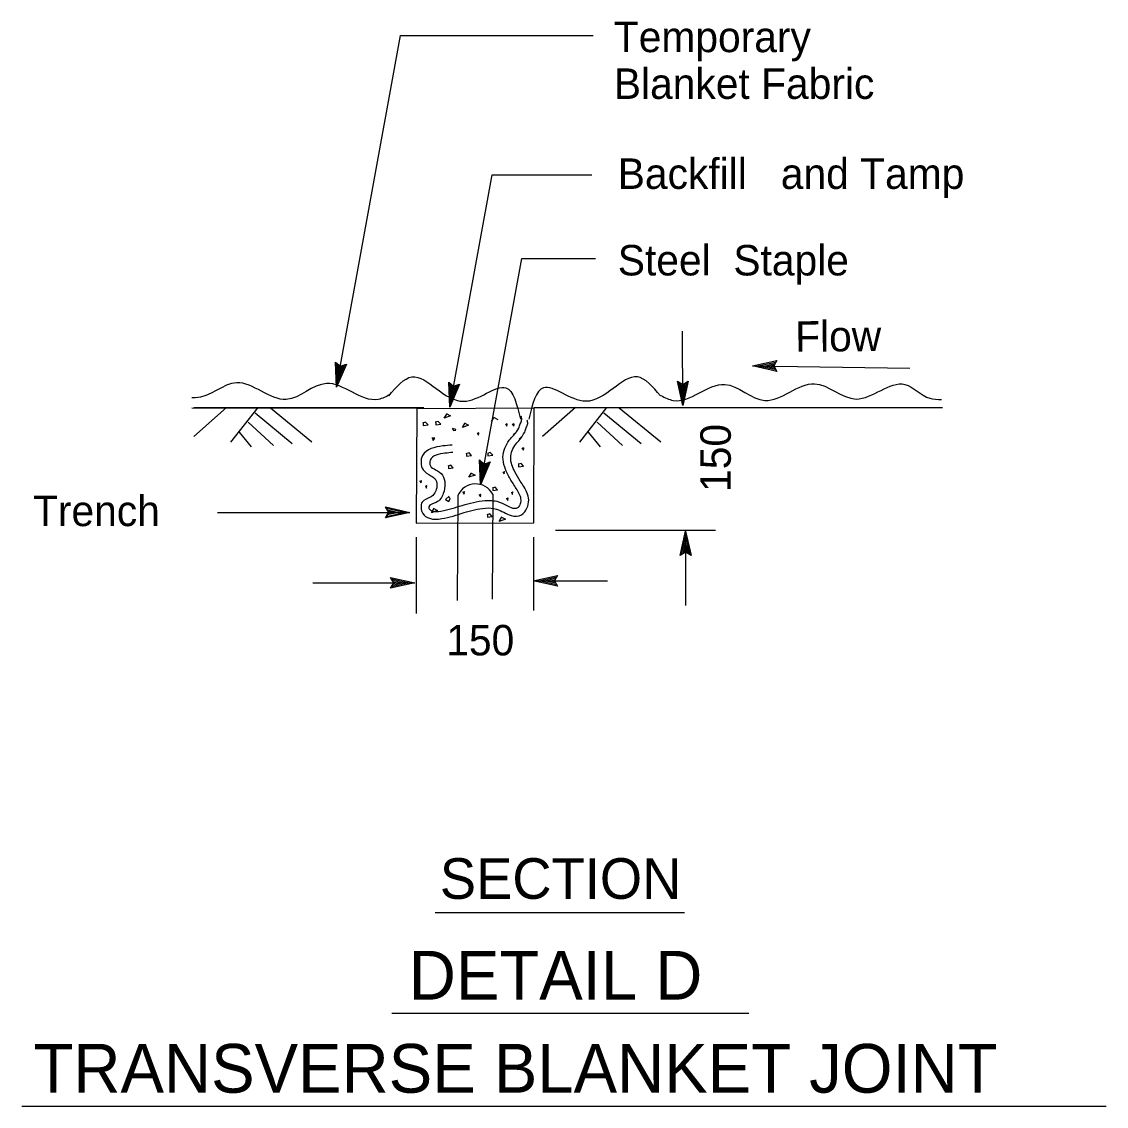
# Model space of a CAD drawing. Extents: x 6712486 to 6713732, y 1869200 to 1869925.
# Drawn here: x 6713210.2 to 6713432.4, y 1869671.9 to 1869894.2 of the extents above; entities that cross this region are included whole.
import ezdxf

# ---------------------------------------------------------------- set-up
doc = ezdxf.new("R2010")
doc.units = 0
for name, color, linetype in [('56 Stg 3 Anno', 7, 'Continuous'), ('57 Undefined', 7, 'Continuous'), ('60 Nongeo Data', 7, 'Continuous'), ('63 Undefined', 7, 'Continuous')]:
    doc.layers.add(name, color=color, linetype=linetype)

msp = doc.modelspace()

# ---------------------------------------------------------------- linework, layer by layer
at = {"layer": '56 Stg 3 Anno'}
for p, q in [((6713274.69, 1869819.32), (6713274.5, 1869824.43)), ((6713274.5, 1869824.43), (6713274.5, 1869824.43)), ((6713274.5, 1869824.43), (6713275.47, 1869823.57)), ((6713276.69, 1869824.03), (6713274.69, 1869819.32)), ((6713274.9, 1869820.45), (6713274.76, 1869824.18)), ((6713276.37, 1869823.9), (6713274.9, 1869820.45)), ((6713275.11, 1869821.58), (6713275.02, 1869823.99)), ((6713276.04, 1869823.77), (6713275.11, 1869821.58)), ((6713275.32, 1869822.71), (6713275.28, 1869823.74)), ((6713275.73, 1869823.67), (6713275.32, 1869822.71)), ((6713275.47, 1869823.57), (6713276.69, 1869824.03)), ((6713276.69, 1869824.03), (6713276.69, 1869824.03)), ((6713359.91, 1869823.63), (6713364.9, 1869824.73)), ((6713364.9, 1869822.51), (6713359.91, 1869823.63)), ((6713359.91, 1869823.63), (6713359.91, 1869823.63)), ((6713364.72, 1869822.81), (6713361.05, 1869823.62)), ((6713361.06, 1869823.63), (6713364.71, 1869824.43)), ((6713362.21, 1869823.62), (6713364.56, 1869824.15)), ((6713364.53, 1869823.11), (6713362.21, 1869823.62)), ((6713363.36, 1869823.62), (6713364.36, 1869823.85)), ((6713364.38, 1869823.39), (6713363.36, 1869823.62)), ((6713364.9, 1869824.73), (6713364.24, 1869823.63)), ((6713364.24, 1869823.63), (6713364.9, 1869822.51)), ((6713364.9, 1869824.73), (6713364.9, 1869824.73)), ((6713364.9, 1869822.51), (6713364.9, 1869822.51)), ((6713274.69, 1869819.32), (6713274.69, 1869819.32)), ((6713297.89, 1869815.2), (6713297.7, 1869820.32)), ((6713297.7, 1869820.32), (6713297.7, 1869820.32)), ((6713297.7, 1869820.32), (6713298.67, 1869819.46)), ((6713299.89, 1869819.91), (6713297.89, 1869815.2)), ((6713298.1, 1869816.34), (6713297.96, 1869820.07)), ((6713299.57, 1869819.79), (6713298.1, 1869816.33)), ((6713298.31, 1869817.46), (6713298.22, 1869819.87)), ((6713299.24, 1869819.65), (6713298.31, 1869817.46)), ((6713298.52, 1869818.59), (6713298.48, 1869819.63)), ((6713298.93, 1869819.56), (6713298.52, 1869818.59)), ((6713298.67, 1869819.46), (6713299.89, 1869819.91)), ((6713299.89, 1869819.91), (6713299.89, 1869819.91)), ((6713345.61, 1869815.52), (6713344.51, 1869820.51)), ((6713344.51, 1869820.51), (6713344.51, 1869820.51)), ((6713344.51, 1869820.51), (6713345.61, 1869819.85)), ((6713345.61, 1869816.67), (6713344.8, 1869820.32)), ((6713345.61, 1869817.82), (6713345.09, 1869820.17)), ((6713345.62, 1869818.97), (6713345.39, 1869819.97)), ((6713345.61, 1869819.85), (6713346.73, 1869820.51)), ((6713346.73, 1869820.51), (6713345.61, 1869815.52)), ((6713346.43, 1869820.33), (6713345.61, 1869816.66)), ((6713346.13, 1869820.14), (6713345.61, 1869817.82)), ((6713345.84, 1869819.99), (6713345.62, 1869818.97)), ((6713346.73, 1869820.51), (6713346.73, 1869820.51)), ((6713297.89, 1869815.2), (6713297.89, 1869815.2)), ((6713345.61, 1869815.52), (6713345.61, 1869815.52)), ((6713304.17, 1869799.26), (6713303.98, 1869804.37)), ((6713303.98, 1869804.37), (6713303.98, 1869804.37)), ((6713303.98, 1869804.37), (6713304.95, 1869803.52)), ((6713306.17, 1869803.97), (6713304.17, 1869799.26)), ((6713304.38, 1869800.4), (6713304.24, 1869804.13)), ((6713305.84, 1869803.85), (6713304.38, 1869800.39)), ((6713304.59, 1869801.52), (6713304.5, 1869803.93)), ((6713305.51, 1869803.71), (6713304.59, 1869801.52)), ((6713304.8, 1869802.65), (6713304.76, 1869803.68)), ((6713305.2, 1869803.62), (6713304.8, 1869802.65)), ((6713304.95, 1869803.52), (6713306.17, 1869803.97)), ((6713306.17, 1869803.97), (6713306.17, 1869803.97)), ((6713304.17, 1869799.26), (6713304.17, 1869799.26)), ((6713345.09, 1869784.79), (6713346.2, 1869789.79)), ((6713346.2, 1869789.79), (6713346.2, 1869789.79)), ((6713346.2, 1869789.79), (6713347.31, 1869784.79)), ((6713345.38, 1869784.98), (6713346.2, 1869788.64)), ((6713345.68, 1869785.17), (6713346.2, 1869787.49)), ((6713346.2, 1869787.49), (6713346.72, 1869785.14)), ((6713346.21, 1869788.63), (6713347.01, 1869784.99)), ((6713346.2, 1869785.46), (6713345.09, 1869784.79)), ((6713345.97, 1869785.32), (6713346.2, 1869786.34)), ((6713346.2, 1869786.34), (6713346.43, 1869785.33)), ((6713347.31, 1869784.79), (6713346.2, 1869785.46)), ((6713345.09, 1869784.79), (6713345.09, 1869784.79)), ((6713347.31, 1869784.79), (6713347.31, 1869784.79)), ((6713314.99, 1869779.62), (6713319.98, 1869780.73)), ((6713319.98, 1869780.73), (6713319.31, 1869779.62)), ((6713319.98, 1869780.73), (6713319.98, 1869780.73)), ((6713286.39, 1869779.2), (6713285.73, 1869780.32)), ((6713285.73, 1869780.32), (6713285.73, 1869780.32)), ((6713285.73, 1869780.32), (6713290.72, 1869779.2)), ((6713290.72, 1869779.2), (6713285.73, 1869778.09)), ((6713285.73, 1869778.09), (6713286.39, 1869779.2)), ((6713285.91, 1869780.02), (6713289.58, 1869779.2)), ((6713289.57, 1869779.2), (6713285.92, 1869778.39)), ((6713288.42, 1869779.2), (6713286.07, 1869778.68)), ((6713286.1, 1869779.72), (6713288.42, 1869779.2)), ((6713286.25, 1869779.43), (6713287.27, 1869779.2)), ((6713287.27, 1869779.2), (6713286.27, 1869778.98)), ((6713290.72, 1869779.2), (6713290.72, 1869779.2)), ((6713319.98, 1869778.51), (6713314.99, 1869779.62)), ((6713314.99, 1869779.62), (6713314.99, 1869779.62)), ((6713319.8, 1869778.8), (6713316.13, 1869779.62)), ((6713316.14, 1869779.62), (6713319.79, 1869780.43)), ((6713317.29, 1869779.62), (6713319.64, 1869780.14)), ((6713319.61, 1869779.1), (6713317.29, 1869779.62)), ((6713318.44, 1869779.62), (6713319.44, 1869779.84)), ((6713319.46, 1869779.39), (6713318.44, 1869779.62)), ((6713319.31, 1869779.62), (6713319.98, 1869778.51)), ((6713319.98, 1869778.51), (6713319.98, 1869778.51)), ((6713285.73, 1869778.09), (6713285.73, 1869778.09))]:
    msp.add_line(p, q, dxfattribs=at)
at = {"layer": '57 Undefined'}
for p, q in [((6713294.87, 1869711.66), (6713345.94, 1869711.66)), ((6713285.98, 1869691.01), (6713359.18, 1869691.01)), ((6713210.18, 1869671.94), (6713432.38, 1869671.94))]:
    msp.add_line(p, q, dxfattribs=at)
at = {"layer": '60 Nongeo Data'}
for p, q in [((6713274.69, 1869819.32), (6713287.79, 1869891.36)), ((6713287.79, 1869891.36), (6713327.24, 1869891.36)), ((6713297.89, 1869815.2), (6713306.54, 1869862.79)), ((6713306.54, 1869862.79), (6713326.98, 1869862.79)), ((6713304.17, 1869799.26), (6713312.61, 1869845.68)), ((6713312.61, 1869845.68), (6713327.72, 1869845.68)), ((6713345.61, 1869815.52), (6713345.54, 1869830.74)), ((6713359.91, 1869823.63), (6713392.15, 1869823.18)), ((6713252.15, 1869815.14), (6713245.43, 1869809.16)), ((6713245.43, 1869815.12), (6713292.6, 1869815.12)), ((6713258.53, 1869815.1), (6713252.98, 1869808.04)), ((6713257.98, 1869814.04), (6713265.58, 1869807.78)), ((6713261.12, 1869815.07), (6713269.62, 1869808.07)), ((6713291.21, 1869814.89), (6713315.17, 1869815.07)), ((6713323.63, 1869815.14), (6713316.91, 1869809.16)), ((6713316.91, 1869815.12), (6713364.08, 1869815.12)), ((6713330.01, 1869815.1), (6713324.46, 1869808.04)), ((6713329.46, 1869814.04), (6713337.06, 1869807.78)), ((6713332.6, 1869815.07), (6713341.1, 1869808.07)), ((6713256.59, 1869812.09), (6713261.78, 1869807.37)), ((6713292.94, 1869812.09), (6713292.32, 1869811.91)), ((6713292.44, 1869812.03), (6713292.44, 1869811.42)), ((6713293.43, 1869811.54), (6713292.94, 1869812.09)), ((6713295.53, 1869812.28), (6713294.91, 1869812.09)), ((6713295.03, 1869812.22), (6713295.03, 1869811.6)), ((6713296.02, 1869811.72), (6713295.53, 1869812.28)), ((6713296.76, 1869812.96), (6713297.25, 1869813.76)), ((6713298.05, 1869813.39), (6713296.76, 1869812.96)), ((6713297.13, 1869813.88), (6713298.05, 1869813.39)), ((6713300.46, 1869811.05), (6713300.95, 1869811.85)), ((6713300.83, 1869811.97), (6713301.75, 1869811.48)), ((6713306.44, 1869812.22), (6713306.93, 1869813.02)), ((6713306.81, 1869813.14), (6713307.73, 1869812.65)), ((6713328.07, 1869812.09), (6713333.26, 1869807.37)), ((6713254.75, 1869810.07), (6713257.18, 1869807.08)), ((6713292.44, 1869811.42), (6713293.43, 1869811.54)), ((6713295.03, 1869811.6), (6713296.02, 1869811.72)), ((6713298.36, 1869810.86), (6713298.67, 1869810.43)), ((6713298.36, 1869810.86), (6713299.04, 1869810.68)), ((6713298.67, 1869810.43), (6713299.1, 1869810.49)), ((6713299.1, 1869810.49), (6713299.04, 1869810.68)), ((6713301.75, 1869811.48), (6713300.46, 1869811.05)), ((6713303.82, 1869809.91), (6713303.48, 1869809.76)), ((6713303.54, 1869809.82), (6713303.79, 1869809.45)), ((6713303.79, 1869809.45), (6713303.85, 1869809.94)), ((6713303.85, 1869809.94), (6713303.79, 1869809.88)), ((6713309.62, 1869811.76), (6713309.28, 1869811.6)), ((6713309.34, 1869811.66), (6713309.58, 1869811.29)), ((6713309.58, 1869811.29), (6713309.65, 1869811.79)), ((6713309.65, 1869811.79), (6713309.58, 1869811.72)), ((6713311.03, 1869811.76), (6713310.69, 1869811.6)), ((6713310.76, 1869811.66), (6713311, 1869811.29)), ((6713311, 1869811.29), (6713311.06, 1869811.79)), ((6713311.06, 1869811.79), (6713311, 1869811.72)), ((6713326.23, 1869810.07), (6713328.66, 1869807.08)), ((6713294.79, 1869808.83), (6713294.23, 1869808.83)), ((6713294.29, 1869808.89), (6713294.48, 1869808.34)), ((6713294.48, 1869808.34), (6713294.79, 1869808.83)), ((6713301.82, 1869805.82), (6713301.2, 1869805.63)), ((6713301.32, 1869805.76), (6713301.32, 1869805.14)), ((6713301.32, 1869805.14), (6713302.31, 1869805.26)), ((6713302.31, 1869805.26), (6713301.82, 1869805.82)), ((6713306.19, 1869805.88), (6713305.58, 1869805.69)), ((6713305.7, 1869805.82), (6713305.7, 1869805.2)), ((6713305.7, 1869805.2), (6713306.69, 1869805.33)), ((6713306.69, 1869805.33), (6713306.19, 1869805.88)), ((6713313.01, 1869806.83), (6713312.67, 1869806.68)), ((6713312.73, 1869806.74), (6713312.97, 1869806.37)), ((6713312.97, 1869806.37), (6713313.04, 1869806.86)), ((6713313.04, 1869806.86), (6713312.97, 1869806.8)), ((6713298.12, 1869803.29), (6713297.5, 1869803.11)), ((6713297.62, 1869803.23), (6713297.62, 1869802.62)), ((6713298.61, 1869802.74), (6713298.12, 1869803.29)), ((6713312.48, 1869803.66), (6713311.86, 1869803.48)), ((6713311.99, 1869803.6), (6713311.99, 1869802.99)), ((6713311.99, 1869802.99), (6713312.97, 1869803.11)), ((6713312.97, 1869803.11), (6713312.48, 1869803.66)), ((6713297.62, 1869802.62), (6713298.61, 1869802.74)), ((6713301.77, 1869800.82), (6713302.26, 1869801.62)), ((6713303.07, 1869801.25), (6713301.77, 1869800.82)), ((6713302.14, 1869801.74), (6713303.07, 1869801.25)), ((6713309.06, 1869801.97), (6713308.72, 1869801.82)), ((6713308.78, 1869801.88), (6713309.03, 1869801.51)), ((6713309.03, 1869801.51), (6713309.09, 1869802)), ((6713309.09, 1869802), (6713309.03, 1869801.94)), ((6713292.04, 1869800.13), (6713291.7, 1869799.97)), ((6713291.77, 1869800.03), (6713292.01, 1869799.66)), ((6713292.01, 1869799.66), (6713292.07, 1869800.16)), ((6713292.07, 1869800.16), (6713292.01, 1869800.1)), ((6713293.15, 1869799.08), (6713292.81, 1869798.93)), ((6713292.88, 1869798.99), (6713293.12, 1869798.62)), ((6713293.12, 1869798.62), (6713293.18, 1869799.11)), ((6713293.18, 1869799.11), (6713293.12, 1869799.05)), ((6713307.18, 1869798.8), (6713306.56, 1869798.62)), ((6713306.69, 1869798.74), (6713306.69, 1869798.13)), ((6713307.67, 1869798.25), (6713307.18, 1869798.8)), ((6713297.75, 1869796.96), (6713297.01, 1869796.28)), ((6713297.01, 1869796.28), (6713297.68, 1869795.85)), ((6713297.99, 1869796.47), (6713297.68, 1869796.77)), ((6713297.68, 1869795.85), (6713297.99, 1869796.47)), ((6713299.46, 1869775.56), (6713299.61, 1869797.13)), ((6713300.86, 1869797.85), (6713300.52, 1869797.7)), ((6713300.58, 1869797.76), (6713300.83, 1869797.39)), ((6713300.83, 1869797.39), (6713300.89, 1869797.88)), ((6713300.89, 1869797.88), (6713300.83, 1869797.82)), ((6713304.19, 1869797.3), (6713303.85, 1869797.14)), ((6713303.91, 1869797.2), (6713304.16, 1869796.83)), ((6713304.16, 1869796.83), (6713304.22, 1869797.33)), ((6713304.22, 1869797.33), (6713304.16, 1869797.27)), ((6713306.69, 1869797.38), (6713306.54, 1869775.82)), ((6713306.69, 1869798.13), (6713307.67, 1869798.25)), ((6713309.8, 1869796.56), (6713309.46, 1869796.4)), ((6713309.52, 1869796.47), (6713309.77, 1869796.1)), ((6713309.77, 1869796.1), (6713309.83, 1869796.59)), ((6713309.83, 1869796.59), (6713309.77, 1869796.53)), ((6713310.79, 1869797.79), (6713310.45, 1869797.63)), ((6713310.51, 1869797.7), (6713310.76, 1869797.33)), ((6713310.76, 1869797.33), (6713310.82, 1869797.82)), ((6713310.82, 1869797.82), (6713310.76, 1869797.76)), ((6713294.11, 1869793.57), (6713294.6, 1869794.37)), ((6713294.48, 1869794.5), (6713295.4, 1869794)), ((6713250.27, 1869793.63), (6713289.72, 1869793.63)), ((6713295.4, 1869794), (6713294.11, 1869793.57)), ((6713306.07, 1869793.33), (6713305.45, 1869793.14)), ((6713305.58, 1869793.27), (6713305.58, 1869792.65)), ((6713305.58, 1869792.65), (6713306.56, 1869792.77)), ((6713306.56, 1869792.77), (6713306.07, 1869793.33)), ((6713307.98, 1869791.79), (6713308.47, 1869792.59)), ((6713309.28, 1869792.22), (6713307.98, 1869791.79)), ((6713308.35, 1869792.71), (6713309.28, 1869792.22)), ((6713319.57, 1869790.02), (6713352.35, 1869790.02)), ((6713346.2, 1869789.79), (6713346.18, 1869774.57)), ((6713291.02, 1869788.58), (6713291.01, 1869772.9)), ((6713315.06, 1869788.57), (6713315.05, 1869773.5)), ((6713269.83, 1869779.2), (6713290.72, 1869779.2)), ((6713314.99, 1869779.62), (6713330.21, 1869779.62))]:
    msp.add_line(p, q, dxfattribs=at)
msp.add_lwpolyline([(6713245.01, 1869815.06), (6713291.1, 1869814.97), (6713290.98, 1869791.45), (6713315.09, 1869791.46), (6713315.18, 1869815.15), (6713398.84, 1869815.15)], dxfattribs=at)
msp.add_arc((6713303.19, 1869795.45), 4.01, 28.8752, 155.8761, dxfattribs=at)
for points in [[(6713285.39, 1869817.51), (6713290.13, 1869821.4), (6713300.71, 1869816.39), (6713309.35, 1869819.17), (6713312.36, 1869812.74)], [(6713341.05, 1869817.51), (6713336.31, 1869821.4), (6713325.73, 1869816.39), (6713317.09, 1869819.17), (6713314.08, 1869812.74)], [(6713285.69, 1869817.79), (6713283.22, 1869816.77), (6713272.61, 1869820.05), (6713264.39, 1869816.77), (6713254.24, 1869820.2), (6713245.72, 1869817.07), (6713245.01, 1869817.09)], [(6713341.15, 1869817.58), (6713343.63, 1869816.57), (6713354.23, 1869819.85), (6713362.45, 1869816.57), (6713372.6, 1869820), (6713381.12, 1869816.86), (6713391.13, 1869819.85), (6713396.2, 1869817.01), (6713398.64, 1869816.79)], [(6713310.91, 1869809.48), (6713312.01, 1869810.91), (6713312.32, 1869811.77), (6713312.63, 1869812.63), (6713312.51, 1869813.37)], [(6713312.12, 1869808.67), (6713313.23, 1869810.1), (6713313.54, 1869810.96), (6713313.84, 1869811.83), (6713313.72, 1869812.56)], [(6713298.49, 1869805.91), (6713296.9, 1869805.75), (6713293.86, 1869804.32), (6713293.91, 1869803.16), (6713294.96, 1869802.36), (6713296.37, 1869801.25), (6713296.56, 1869797.52), (6713295.11, 1869795.68), (6713293.58, 1869794.76), (6713293.56, 1869794.69), (6713293.67, 1869794.33), (6713294.22, 1869793.93), (6713296.06, 1869793.89), (6713300.44, 1869795.07), (6713305.08, 1869796.05), (6713307.85, 1869795.82), (6713309.57, 1869795.04), (6713310.74, 1869794.53), (6713311.8, 1869794.62), (6713312.27, 1869795.19), (6713312.49, 1869796.16), (6713312.25, 1869797.13), (6713311.01, 1869799.28), (6713309.86, 1869801.26), (6713309.13, 1869802.93), (6713308.78, 1869805), (6713310.07, 1869808.41), (6713311.06, 1869809.54), (6713311.49, 1869810.04)], [(6713298.34, 1869807.43), (6713296.49, 1869807.24), (6713292.29, 1869805.28), (6713292.42, 1869802.38), (6713294.02, 1869801.15), (6713294.88, 1869800.48), (6713295.01, 1869798.02), (6713294.08, 1869796.85), (6713292.23, 1869795.74), (6713291.99, 1869794.63), (6713292.35, 1869793.4), (6713293.71, 1869792.42), (6713296.24, 1869792.35), (6713300.8, 1869793.58), (6713305.18, 1869794.51), (6713307.46, 1869794.32), (6713308.94, 1869793.65), (6713310.48, 1869792.97), (6713312.58, 1869793.15), (6713313.69, 1869794.51), (6713314.06, 1869796.17), (6713313.69, 1869797.71), (6713312.33, 1869800.05), (6713311.22, 1869801.95), (6713310.6, 1869803.37), (6713310.36, 1869804.84), (6713311.41, 1869807.61), (6713312.21, 1869808.54), (6713312.64, 1869809.03)]]:
    msp.add_spline(points, degree=3, dxfattribs=at)
at = {"layer": '63 Undefined'}
for p, q in [((6713284.73, 1869794.74), (6713284.73, 1869794.74)), ((6713284.73, 1869792.52), (6713284.73, 1869792.52)), ((6713289.72, 1869793.63), (6713289.72, 1869793.63))]:
    msp.add_line(p, q, dxfattribs=at)
msp.add_lwpolyline([(6713284.73, 1869794.74), (6713289.72, 1869793.63), (6713284.73, 1869792.52), (6713284.9, 1869792.82), (6713288.56, 1869793.63), (6713284.9, 1869794.45), (6713285.08, 1869794.15), (6713287.42, 1869793.63), (6713285.08, 1869793.11), (6713285.26, 1869793.41), (6713286.27, 1869793.63), (6713285.26, 1869793.86), (6713285.39, 1869793.63), (6713284.73, 1869792.52), (6713285.39, 1869793.63)], close=True, dxfattribs=at)

# ---------------------------------------------------------------- texts
at = {"layer": '57 Undefined'}
for s, height, p in [('SECTION', 8.327, (6713295.84, 1869714.45)), ('DETAIL D', 9.992, (6713289.48, 1869693.8)), ('TRANSVERSE BLANKET JOINT', 9.9921, (6713212.61, 1869674.73))]:
    msp.add_text(s, height=height, dxfattribs=at).set_placement(p)
at = {"layer": '60 Nongeo Data'}
for s, height, p in [('Temporary ', 6.245, (6713331.49, 1869887.93)), ('Blanket Fabric', 6.2451, (6713331.49, 1869878.35)), ('Backfill   and Tamp', 6.2451, (6713332.29, 1869859.91)), ('Steel  Staple', 6.2451, (6713332.3, 1869842.18)), ('Trench', 6.245, (6713212.49, 1869790.82)), ('150 ', 6.245, (6713297.16, 1869764.33))]:
    msp.add_text(s, height=height, dxfattribs=at).set_placement(p)
for s, rotation, p in [('Flow', 0.4741, (6713368.66, 1869826.54)), ('150 ', 89.9718, (6713355.45, 1869797.82))]:
    msp.add_text(s, height=6.245, rotation=rotation, dxfattribs=at).set_placement(p)

doc.saveas('drawing.dxf')
